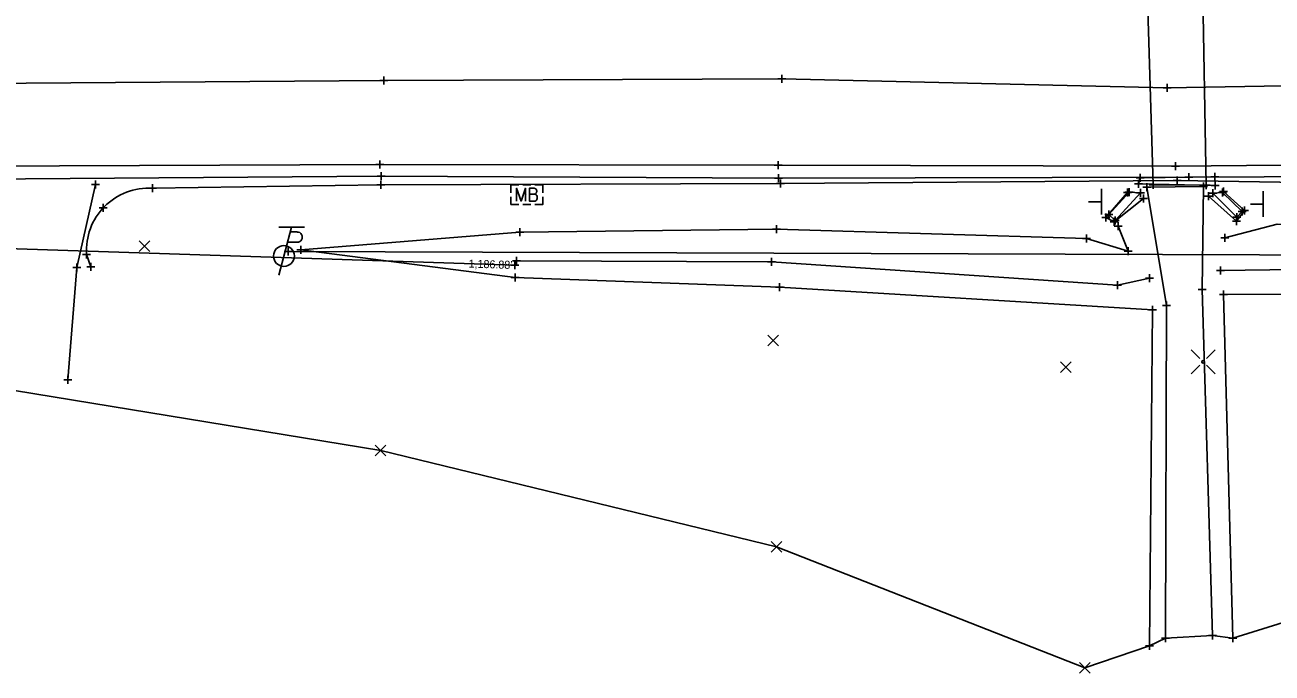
# Model space of a CAD drawing. Extents: x 2319153 to 2321514, y 575338 to 575500.
# Drawn here: x 2320670.1 to 2320825.9, y 575338.3 to 575419.3 of the extents above; entities that cross this region are included whole.
import ezdxf

# ---------------------------------------------------------------- set-up
doc = ezdxf.new("R2010")
doc.units = 0
for name, color, linetype in [('Default', 7, 'Continuous'), ('DR_X_Culvert', 7, 'Continuous'), ('DR_X_Ditch', 7, 'Continuous'), ('DR_X_Elev_Flow', 7, 'Continuous'), ('DR_X_Headwall', 7, 'Continuous'), ('DR_X_Storm_Sewer', 7, 'Continuous'), ('PV_X_COP', 7, 'Continuous'), ('PV_X_Driveway', 7, 'Continuous'), ('PV_X_EOP', 7, 'Continuous'), ('PV_X_Shoulder', 7, 'Continuous'), ('RD_X_Cells', 7, 'Continuous'), ('RD_X_GR_Lt', 7, 'Continuous'), ('RD_X_Wall', 7, 'Continuous'), ('SC_Scratch1', 7, 'Continuous'), ('SN_X_Public', 7, 'Continuous'), ('SV_X_Break_Lines', 7, 'Continuous'), ('SV_X_Control_Cells_Found', 7, 'Continuous'), ('SV_X_Random_Point', 7, 'Continuous'), ('SV_X_Shot_Marker', 7, 'Continuous'), ('SV_X_Terrain_Boundary', 7, 'Continuous'), ('UT_X_Misc_Cells', 7, 'Continuous'), ('UT_X_Telecom', 7, 'Continuous')]:
    doc.layers.add(name, color=color, linetype=linetype)

msp = doc.modelspace()

# ---------------------------------------------------------------- linework, layer by layer
at = {"layer": 'Default'}
msp.add_line((2320731.3, 575389.3), (2320731.3, 575389.3), dxfattribs=at)
at = {"layer": 'DR_X_Culvert'}
msp.add_lwpolyline([(2320811.09, 575399.31), (2320817.7, 575399.29), (2320817.26, 575425.4), (2320810.29, 575425.41)], close=True, dxfattribs=at)
at = {"layer": 'DR_X_Ditch'}
for points in [[(2320818.49, 575343.02), (2320817.18, 575386.25), (2320817.36, 575399.11), (2320810.28, 575399.02), (2320812.75, 575384.26), (2320812.62, 575342.69)], [(2320810.6, 575387.65), (2320806.62, 575386.77), (2320763.39, 575389.72), (2320731.5, 575389.84)], [(2320953.76, 575387.79), (2320916.54, 575387.63), (2320862.79, 575389.2), (2320819.49, 575388.61)]]:
    msp.add_lwpolyline(points, dxfattribs=at)
at = {"layer": 'DR_X_Elev_Flow'}
for p, q in [((2320730.8, 575389.3), (2320731.8, 575389.3)), ((2320731.3, 575389.8), (2320731.3, 575388.8)), ((2320731.3, 575389.3), (2320731.3, 575389.3))]:
    msp.add_line(p, q, dxfattribs=at)
at = {"layer": 'DR_X_Headwall'}
msp.add_lwpolyline([(2320809.22, 575399.45), (2320818.82, 575399.25), (2320818.77, 575400.32), (2320809.45, 575400.21)], close=True, dxfattribs=at)
at = {"layer": 'DR_X_Storm_Sewer'}
msp.add_line((2320553.26, 575395.15), (2320731.3, 575389.3), dxfattribs=at)
at = {"layer": 'PV_X_COP'}
msp.add_lwpolyline([(2320664.58, 575411.98), (2320714.9, 575412.38), (2320764.67, 575412.55), (2320812.81, 575411.44), (2320863.71, 575412.31), (2320912.72, 575411.78), (2321003.29, 575411.48), (2321063.97, 575411.74), (2321113.08, 575411.94), (2321163.31, 575411.56), (2321212.82, 575411.61), (2321262.91, 575411.78), (2321313.37, 575411.56), (2321362.17, 575411.58), (2321412.59, 575412.78), (2321463.09, 575413.59), (2321512.4, 575413.87)], dxfattribs=at)
at = {"layer": 'PV_X_Driveway'}
msp.add_lwpolyline([(2320675.41, 575374.96), (2320676.53, 575388.98), (2320678.88, 575399.37)], dxfattribs=at)
at = {"layer": 'PV_X_EOP'}
msp.add_lwpolyline([(2321512.27, 575403.63), (2321462.49, 575403.2), (2321412.87, 575402.74), (2321362.69, 575401.87), (2321312.5, 575402.02), (2321262.43, 575401.63), (2321211.98, 575401.55), (2321107.93, 575402.06), (2321016.27, 575401.73), (2320963.04, 575401.8), (2320913.34, 575401.45), (2320862.76, 575402.1), (2320813.85, 575401.67), (2320764.22, 575401.77), (2320714.4, 575401.87), (2320664.35, 575401.67)], dxfattribs=at)
at = {"layer": 'PV_X_Shoulder'}
msp.add_lwpolyline([(2321513.03, 575401.02), (2321462.24, 575401.09), (2321412.23, 575401.08), (2321362.25, 575400.75), (2321312.5, 575400.39), (2321262.08, 575400.08), (2321212.3, 575399.81), (2321130.87, 575399.59), (2321095.99, 575399.76), (2321032.33, 575399.84), (2320996.03, 575397.56), (2320957.29, 575398.14), (2320912.73, 575400.28), (2320862.68, 575400.51), (2320815.54, 575400.3), (2320764.25, 575400.14), (2320714.58, 575400.4), (2320664.56, 575400.05)], dxfattribs=at)
at = {"layer": 'RD_X_Cells'}
for p, q in [((2320732.28, 575399.31), (2320733.29, 575399.31)), ((2320732.8, 575398.09), (2320732.8, 575398.09)), ((2320732.28, 575396.87), (2320733.29, 575396.87))]:
    msp.add_line(p, q, dxfattribs=at)
for points in [[(2320730.8, 575398.34), (2320730.8, 575399.31), (2320731.77, 575399.31)], [(2320731.5, 575397.29), (2320731.5, 575398.89), (2320732.08, 575397.29), (2320732.63, 575398.89), (2320732.63, 575397.29)], [(2320733.82, 575398.16), (2320733.88, 575398.22), (2320733.92, 575398.26), (2320733.94, 575398.3), (2320733.96, 575398.32), (2320733.98, 575398.37), (2320733.99, 575398.41), (2320734.02, 575398.5), (2320734.02, 575398.54), (2320734.02, 575398.59), (2320734.01, 575398.66), (2320733.98, 575398.73), (2320733.94, 575398.78), (2320733.88, 575398.83), (2320733.83, 575398.85), (2320733.8, 575398.86), (2320733.74, 575398.89), (2320733.12, 575398.89), (2320733.12, 575397.29), (2320733.82, 575397.29), (2320733.91, 575397.34), (2320733.98, 575397.4), (2320734.04, 575397.5), (2320734.08, 575397.62), (2320734.09, 575397.73), (2320734.09, 575397.81), (2320734.07, 575397.88), (2320734.02, 575398), (2320733.96, 575398.07), (2320733.82, 575398.16), (2320733.12, 575398.16)], [(2320733.8, 575399.31), (2320734.8, 575399.31), (2320734.8, 575398.34)], [(2320731.77, 575396.87), (2320730.8, 575396.87), (2320730.8, 575397.84)], [(2320734.8, 575397.84), (2320734.8, 575396.87), (2320733.8, 575396.87)]]:
    msp.add_lwpolyline(points, dxfattribs=at)
at = {"layer": 'RD_X_GR_Lt'}
for p, q in [((2320714.55, 575399.31), (2320686, 575398.89)), ((2320764.49, 575399.47), (2320714.55, 575399.31)), ((2320814.09, 575399.86), (2320764.49, 575399.47)), ((2320863.05, 575399.02), (2320814.09, 575399.86)), ((2320677.77, 575390.61), (2320678.28, 575389.09))]:
    msp.add_line(p, q, dxfattribs=at)
msp.add_arc((2320685.5, 575391.15), 7.75, 86.3475, 183.989, dxfattribs=at)
at = {"layer": 'RD_X_Wall'}
for points in [[(2320808.08, 575398.4), (2320809.5, 575398.32), (2320806.32, 575394.87), (2320805.54, 575395.6)], [(2320818.53, 575398.27), (2320819.73, 575398.36), (2320822.18, 575395.99), (2320821.52, 575395.29)]]:
    msp.add_lwpolyline(points, close=True, dxfattribs=at)
at = {"layer": 'SN_X_Public'}
for p, q in [((2320804.6, 575398.81), (2320804.6, 575395.61)), ((2320824.82, 575398.52), (2320824.82, 575395.32)), ((2320804.6, 575397.21), (2320803, 575397.21)), ((2320824.82, 575396.92), (2320823.22, 575396.92))]:
    msp.add_line(p, q, dxfattribs=at)
at = {"layer": 'SV_X_Break_Lines'}
for points in [[(2320818.01, 575397.92), (2320821.49, 575394.8), (2320822.49, 575396.1), (2320819.88, 575398.5)], [(2320807.87, 575398.38), (2320805.14, 575395.24), (2320806.19, 575394.69), (2320809.87, 575397.61)], [(2320810.61, 575341.7), (2320811, 575383.69), (2320764.38, 575386.52), (2320731.31, 575387.75), (2320704.54, 575391.21), (2320731.92, 575393.41), (2320763.99, 575393.77), (2320802.76, 575392.61), (2320807.95, 575391.04), (2320806.71, 575394.16)], [(2320821.03, 575342.66), (2320819.85, 575385.62), (2320862.23, 575385.84), (2320911.12, 575383.65), (2320954.21, 575383.98), (2320955.99, 575388.6), (2320953.91, 575392.32), (2320912.09, 575392.64), (2320861.66, 575393.79), (2320826.59, 575394.39), (2320820.03, 575392.72)]]:
    msp.add_lwpolyline(points, dxfattribs=at)
at = {"layer": 'SV_X_Control_Cells_Found'}
for p, q in [((2320815.82, 575378.71), (2320816.92, 575377.61)), ((2320817.75, 575377.61), (2320818.84, 575378.71)), ((2320815.82, 575375.69), (2320816.92, 575376.78)), ((2320817.75, 575376.78), (2320818.84, 575375.69))]:
    msp.add_line(p, q, dxfattribs=at)
msp.add_circle((2320817.33, 575377.2), 0.17, dxfattribs=at)
at = {"layer": 'SV_X_Random_Point'}
for p, q in [((2320684.34, 575390.98), (2320685.67, 575392.31)), ((2320684.34, 575392.31), (2320685.67, 575390.98)), ((2320762.92, 575379.2), (2320764.25, 575380.54)), ((2320762.92, 575380.54), (2320764.25, 575379.2)), ((2320799.48, 575375.88), (2320800.81, 575377.22)), ((2320799.48, 575377.22), (2320800.81, 575375.88)), ((2320713.85, 575365.46), (2320715.18, 575366.8)), ((2320713.85, 575366.8), (2320715.18, 575365.46)), ((2320763.34, 575353.41), (2320764.68, 575354.75)), ((2320763.34, 575354.75), (2320764.68, 575353.41)), ((2320801.85, 575338.31), (2320803.19, 575339.64)), ((2320801.85, 575339.64), (2320803.19, 575338.31))]:
    msp.add_line(p, q, dxfattribs=at)
at = {"layer": 'SV_X_Shot_Marker'}
for p, q in [((2320714.9, 575412.88), (2320714.9, 575411.88)), ((2320764.17, 575412.55), (2320765.17, 575412.55)), ((2320764.67, 575413.05), (2320764.67, 575412.05)), ((2320764.67, 575412.55), (2320764.67, 575412.55)), ((2320714.4, 575412.38), (2320715.4, 575412.38)), ((2320714.9, 575412.38), (2320714.9, 575412.38)), ((2320812.31, 575411.44), (2320813.31, 575411.44)), ((2320812.81, 575411.94), (2320812.81, 575410.94)), ((2320812.81, 575411.44), (2320812.81, 575411.44)), ((2320713.9, 575401.87), (2320714.9, 575401.87)), ((2320714.4, 575402.37), (2320714.4, 575401.37)), ((2320714.4, 575401.87), (2320714.4, 575401.87)), ((2320763.72, 575401.77), (2320764.72, 575401.77)), ((2320764.22, 575402.27), (2320764.22, 575401.27)), ((2320764.22, 575401.77), (2320764.22, 575401.77)), ((2320813.35, 575401.67), (2320814.35, 575401.67)), ((2320813.85, 575402.17), (2320813.85, 575401.17)), ((2320813.85, 575401.67), (2320813.85, 575401.67)), ((2320714.08, 575400.4), (2320715.08, 575400.4)), ((2320714.58, 575400.9), (2320714.58, 575399.9)), ((2320714.58, 575400.4), (2320714.58, 575400.4)), ((2320763.75, 575400.14), (2320764.75, 575400.14)), ((2320764.25, 575400.64), (2320764.25, 575399.64)), ((2320764.25, 575400.14), (2320764.25, 575400.14)), ((2320808.95, 575400.21), (2320809.95, 575400.21)), ((2320809.45, 575400.71), (2320809.45, 575399.71)), ((2320809.45, 575400.21), (2320809.45, 575400.21)), ((2320814.09, 575400.36), (2320814.09, 575399.36)), ((2320815.04, 575400.3), (2320816.04, 575400.3)), ((2320815.54, 575400.8), (2320815.54, 575399.8)), ((2320815.54, 575400.3), (2320815.54, 575400.3)), ((2320818.27, 575400.32), (2320819.27, 575400.32)), ((2320818.77, 575400.82), (2320818.77, 575399.82)), ((2320818.77, 575400.32), (2320818.77, 575400.32)), ((2320678.38, 575399.37), (2320679.38, 575399.37)), ((2320678.88, 575399.87), (2320678.88, 575398.87)), ((2320678.88, 575399.37), (2320678.88, 575399.37)), ((2320685.5, 575398.89), (2320686.5, 575398.89)), ((2320686, 575399.39), (2320686, 575398.39)), ((2320686, 575398.89), (2320686, 575398.89)), ((2320714.05, 575399.31), (2320715.05, 575399.31)), ((2320714.55, 575399.81), (2320714.55, 575398.81)), ((2320714.55, 575399.31), (2320714.55, 575399.31)), ((2320763.99, 575399.47), (2320764.99, 575399.47)), ((2320764.49, 575399.97), (2320764.49, 575398.97)), ((2320764.49, 575399.47), (2320764.49, 575399.47)), ((2320807.87, 575398.88), (2320807.87, 575397.88)), ((2320808.08, 575398.9), (2320808.08, 575397.9)), ((2320808.72, 575399.45), (2320809.72, 575399.45)), ((2320809.22, 575399.95), (2320809.22, 575398.95)), ((2320809.22, 575399.45), (2320809.22, 575399.45)), ((2320809.5, 575398.82), (2320809.5, 575397.82)), ((2320809.78, 575399.02), (2320810.78, 575399.02)), ((2320810.28, 575399.52), (2320810.28, 575398.52)), ((2320810.28, 575399.02), (2320810.28, 575399.02)), ((2320810.59, 575399.31), (2320811.59, 575399.31)), ((2320811.09, 575399.81), (2320811.09, 575398.81)), ((2320811.09, 575399.31), (2320811.09, 575399.31)), ((2320813.59, 575399.86), (2320814.59, 575399.86)), ((2320814.09, 575399.86), (2320814.09, 575399.86)), ((2320816.86, 575399.11), (2320817.86, 575399.11)), ((2320817.2, 575399.29), (2320818.2, 575399.29)), ((2320817.36, 575399.61), (2320817.36, 575398.61)), ((2320817.36, 575399.11), (2320817.36, 575399.11)), ((2320817.7, 575399.79), (2320817.7, 575398.79)), ((2320817.7, 575399.29), (2320817.7, 575399.29)), ((2320818.32, 575399.25), (2320819.32, 575399.25)), ((2320818.53, 575398.77), (2320818.53, 575397.77)), ((2320818.82, 575399.75), (2320818.82, 575398.75)), ((2320818.82, 575399.25), (2320818.82, 575399.25)), ((2320819.38, 575398.5), (2320820.38, 575398.5)), ((2320819.73, 575398.86), (2320819.73, 575397.86)), ((2320819.88, 575399), (2320819.88, 575398)), ((2320819.88, 575398.5), (2320819.88, 575398.5)), ((2320679.84, 575396.95), (2320679.84, 575395.95)), ((2320807.37, 575398.38), (2320808.37, 575398.38)), ((2320807.58, 575398.4), (2320808.58, 575398.4)), ((2320807.87, 575398.38), (2320807.87, 575398.38)), ((2320808.08, 575398.4), (2320808.08, 575398.4)), ((2320809, 575398.32), (2320810, 575398.32)), ((2320809.37, 575397.61), (2320810.37, 575397.61)), ((2320809.5, 575398.32), (2320809.5, 575398.32)), ((2320809.87, 575398.11), (2320809.87, 575397.11)), ((2320809.87, 575397.61), (2320809.87, 575397.61)), ((2320817.51, 575397.92), (2320818.51, 575397.92)), ((2320818.01, 575398.42), (2320818.01, 575397.42)), ((2320818.01, 575397.92), (2320818.01, 575397.92)), ((2320818.03, 575398.27), (2320819.03, 575398.27)), ((2320818.53, 575398.27), (2320818.53, 575398.27)), ((2320819.23, 575398.36), (2320820.23, 575398.36)), ((2320819.73, 575398.36), (2320819.73, 575398.36)), ((2320679.34, 575396.45), (2320680.34, 575396.45)), ((2320679.84, 575396.45), (2320679.84, 575396.45)), ((2320805.04, 575395.6), (2320806.04, 575395.6)), ((2320805.14, 575395.74), (2320805.14, 575394.74)), ((2320805.54, 575396.1), (2320805.54, 575395.1)), ((2320805.54, 575395.6), (2320805.54, 575395.6)), ((2320806.32, 575395.37), (2320806.32, 575394.37)), ((2320821.52, 575395.79), (2320821.52, 575394.79)), ((2320821.68, 575395.99), (2320822.68, 575395.99)), ((2320821.99, 575396.1), (2320822.99, 575396.1)), ((2320822.18, 575396.49), (2320822.18, 575395.49)), ((2320822.18, 575395.99), (2320822.18, 575395.99)), ((2320822.49, 575396.6), (2320822.49, 575395.6)), ((2320822.49, 575396.1), (2320822.49, 575396.1)), ((2320731.92, 575393.91), (2320731.92, 575392.91)), ((2320763.99, 575394.27), (2320763.99, 575393.27)), ((2320804.64, 575395.24), (2320805.64, 575395.24)), ((2320805.14, 575395.24), (2320805.14, 575395.24)), ((2320805.69, 575394.69), (2320806.69, 575394.69)), ((2320805.82, 575394.87), (2320806.82, 575394.87)), ((2320806.19, 575395.19), (2320806.19, 575394.19)), ((2320806.19, 575394.69), (2320806.19, 575394.69)), ((2320806.21, 575394.16), (2320807.21, 575394.16)), ((2320806.32, 575394.87), (2320806.32, 575394.87)), ((2320806.71, 575394.66), (2320806.71, 575393.66)), ((2320806.71, 575394.16), (2320806.71, 575394.16)), ((2320820.99, 575394.8), (2320821.99, 575394.8)), ((2320821.02, 575395.29), (2320822.02, 575395.29)), ((2320821.49, 575395.3), (2320821.49, 575394.3)), ((2320821.49, 575394.8), (2320821.49, 575394.8)), ((2320821.52, 575395.29), (2320821.52, 575395.29)), ((2320731.42, 575393.41), (2320732.42, 575393.41)), ((2320731.92, 575393.41), (2320731.92, 575393.41)), ((2320763.49, 575393.77), (2320764.49, 575393.77)), ((2320763.99, 575393.77), (2320763.99, 575393.77)), ((2320802.26, 575392.61), (2320803.26, 575392.61)), ((2320802.76, 575393.11), (2320802.76, 575392.11)), ((2320802.76, 575392.61), (2320802.76, 575392.61)), ((2320819.53, 575392.72), (2320820.53, 575392.72)), ((2320820.03, 575393.22), (2320820.03, 575392.22)), ((2320820.03, 575392.72), (2320820.03, 575392.72)), ((2320677.77, 575391.11), (2320677.77, 575390.11)), ((2320702.46, 575391), (2320703.46, 575391)), ((2320702.96, 575391.5), (2320702.96, 575390.5)), ((2320702.96, 575391), (2320702.96, 575391)), ((2320704.04, 575391.21), (2320705.04, 575391.21)), ((2320704.54, 575391.71), (2320704.54, 575390.71)), ((2320704.54, 575391.21), (2320704.54, 575391.21)), ((2320807.45, 575391.04), (2320808.45, 575391.04)), ((2320807.95, 575391.54), (2320807.95, 575390.54)), ((2320807.95, 575391.04), (2320807.95, 575391.04)), ((2320676.53, 575389.48), (2320676.53, 575388.48)), ((2320677.27, 575390.61), (2320678.27, 575390.61)), ((2320677.77, 575390.61), (2320677.77, 575390.61)), ((2320678.28, 575389.59), (2320678.28, 575388.59)), ((2320731, 575389.84), (2320732, 575389.84)), ((2320731.5, 575390.34), (2320731.5, 575389.34)), ((2320731.5, 575389.84), (2320731.5, 575389.84)), ((2320762.89, 575389.72), (2320763.89, 575389.72)), ((2320763.39, 575390.22), (2320763.39, 575389.22)), ((2320763.39, 575389.72), (2320763.39, 575389.72)), ((2320819.49, 575389.11), (2320819.49, 575388.11)), ((2320676.03, 575388.98), (2320677.03, 575388.98)), ((2320676.53, 575388.98), (2320676.53, 575388.98)), ((2320677.78, 575389.09), (2320678.78, 575389.09)), ((2320678.28, 575389.09), (2320678.28, 575389.09)), ((2320730.81, 575387.75), (2320731.81, 575387.75)), ((2320731.31, 575388.25), (2320731.31, 575387.25)), ((2320731.31, 575387.75), (2320731.31, 575387.75)), ((2320810.1, 575387.65), (2320811.1, 575387.65)), ((2320810.6, 575388.15), (2320810.6, 575387.15)), ((2320810.6, 575387.65), (2320810.6, 575387.65)), ((2320818.99, 575388.61), (2320819.99, 575388.61)), ((2320819.49, 575388.61), (2320819.49, 575388.61)), ((2320763.88, 575386.52), (2320764.88, 575386.52)), ((2320764.38, 575387.02), (2320764.38, 575386.02)), ((2320764.38, 575386.52), (2320764.38, 575386.52)), ((2320806.12, 575386.77), (2320807.12, 575386.77)), ((2320806.62, 575387.27), (2320806.62, 575386.27)), ((2320806.62, 575386.77), (2320806.62, 575386.77)), ((2320816.68, 575386.25), (2320817.68, 575386.25)), ((2320817.18, 575386.75), (2320817.18, 575385.75)), ((2320817.18, 575386.25), (2320817.18, 575386.25)), ((2320819.85, 575386.12), (2320819.85, 575385.12)), ((2320812.75, 575384.76), (2320812.75, 575383.76)), ((2320819.35, 575385.62), (2320820.35, 575385.62)), ((2320819.85, 575385.62), (2320819.85, 575385.62)), ((2320810.5, 575383.69), (2320811.5, 575383.69)), ((2320811, 575384.19), (2320811, 575383.19)), ((2320811, 575383.69), (2320811, 575383.69)), ((2320812.25, 575384.26), (2320813.25, 575384.26)), ((2320812.75, 575384.26), (2320812.75, 575384.26)), ((2320675.41, 575375.46), (2320675.41, 575374.46)), ((2320674.91, 575374.96), (2320675.91, 575374.96)), ((2320675.41, 575374.96), (2320675.41, 575374.96)), ((2320812.12, 575342.69), (2320813.12, 575342.69)), ((2320812.62, 575343.19), (2320812.62, 575342.19)), ((2320812.62, 575342.69), (2320812.62, 575342.69)), ((2320817.99, 575343.02), (2320818.99, 575343.02)), ((2320818.49, 575343.52), (2320818.49, 575342.52)), ((2320818.49, 575343.02), (2320818.49, 575343.02)), ((2320820.53, 575342.66), (2320821.53, 575342.66)), ((2320821.03, 575343.16), (2320821.03, 575342.16)), ((2320821.03, 575342.66), (2320821.03, 575342.66)), ((2320810.11, 575341.7), (2320811.11, 575341.7)), ((2320810.61, 575342.2), (2320810.61, 575341.2)), ((2320810.61, 575341.7), (2320810.61, 575341.7))]:
    msp.add_line(p, q, dxfattribs=at)
at = {"layer": 'SV_X_Terrain_Boundary'}
msp.add_lwpolyline([(2320654.2, 575376.01), (2320714.52, 575366.13), (2320764.01, 575354.08), (2320802.52, 575338.98), (2320810.61, 575341.7), (2320812.62, 575342.69), (2320818.49, 575343.02), (2320821.03, 575342.66), (2320862.94, 575355.7), (2320914.29, 575368.22), (2320960.12, 575369.23), (2320978.33, 575368.17), (2321013.4, 575370.96), (2321062.8, 575369.91), (2321112.71, 575370.23), (2321163.35, 575371.72), (2321212.47, 575372.75), (2321262.08, 575400.08)], dxfattribs=at)
at = {"layer": 'UT_X_Misc_Cells'}
for p, q in [((2320703.39, 575394.03), (2320701.78, 575388.03)), ((2320704.99, 575394.03), (2320701.79, 575394.03)), ((2320703.23, 575393.43), (2320704.08, 575393.43)), ((2320702.89, 575392.15), (2320704.08, 575392.15))]:
    msp.add_line(p, q, dxfattribs=at)
msp.add_circle((2320702.43, 575390.43), 1.3, dxfattribs=at)
msp.add_arc((2320704.09, 575392.79), 0.638, 268.8767, 91.1233, dxfattribs=at)
at = {"layer": 'UT_X_Telecom'}
msp.add_lwpolyline([(2320702.96, 575391), (2320872.93, 575390.42)], dxfattribs=at)

# ---------------------------------------------------------------- texts
at = {"layer": 'SC_Scratch1'}
msp.add_text("1,186.88'", height=1, rotation=358.1199, dxfattribs=at).set_placement((2320725.5, 575388.99))

doc.saveas('drawing.dxf')
